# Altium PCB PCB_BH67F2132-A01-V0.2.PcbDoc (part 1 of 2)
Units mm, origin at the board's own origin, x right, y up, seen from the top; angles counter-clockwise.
Board outline 91.52 x 58.18 mm, 2 copper layers (Top Layer, Bottom Layer); 21 components, 47 nets, 172 pads, 84 vias.
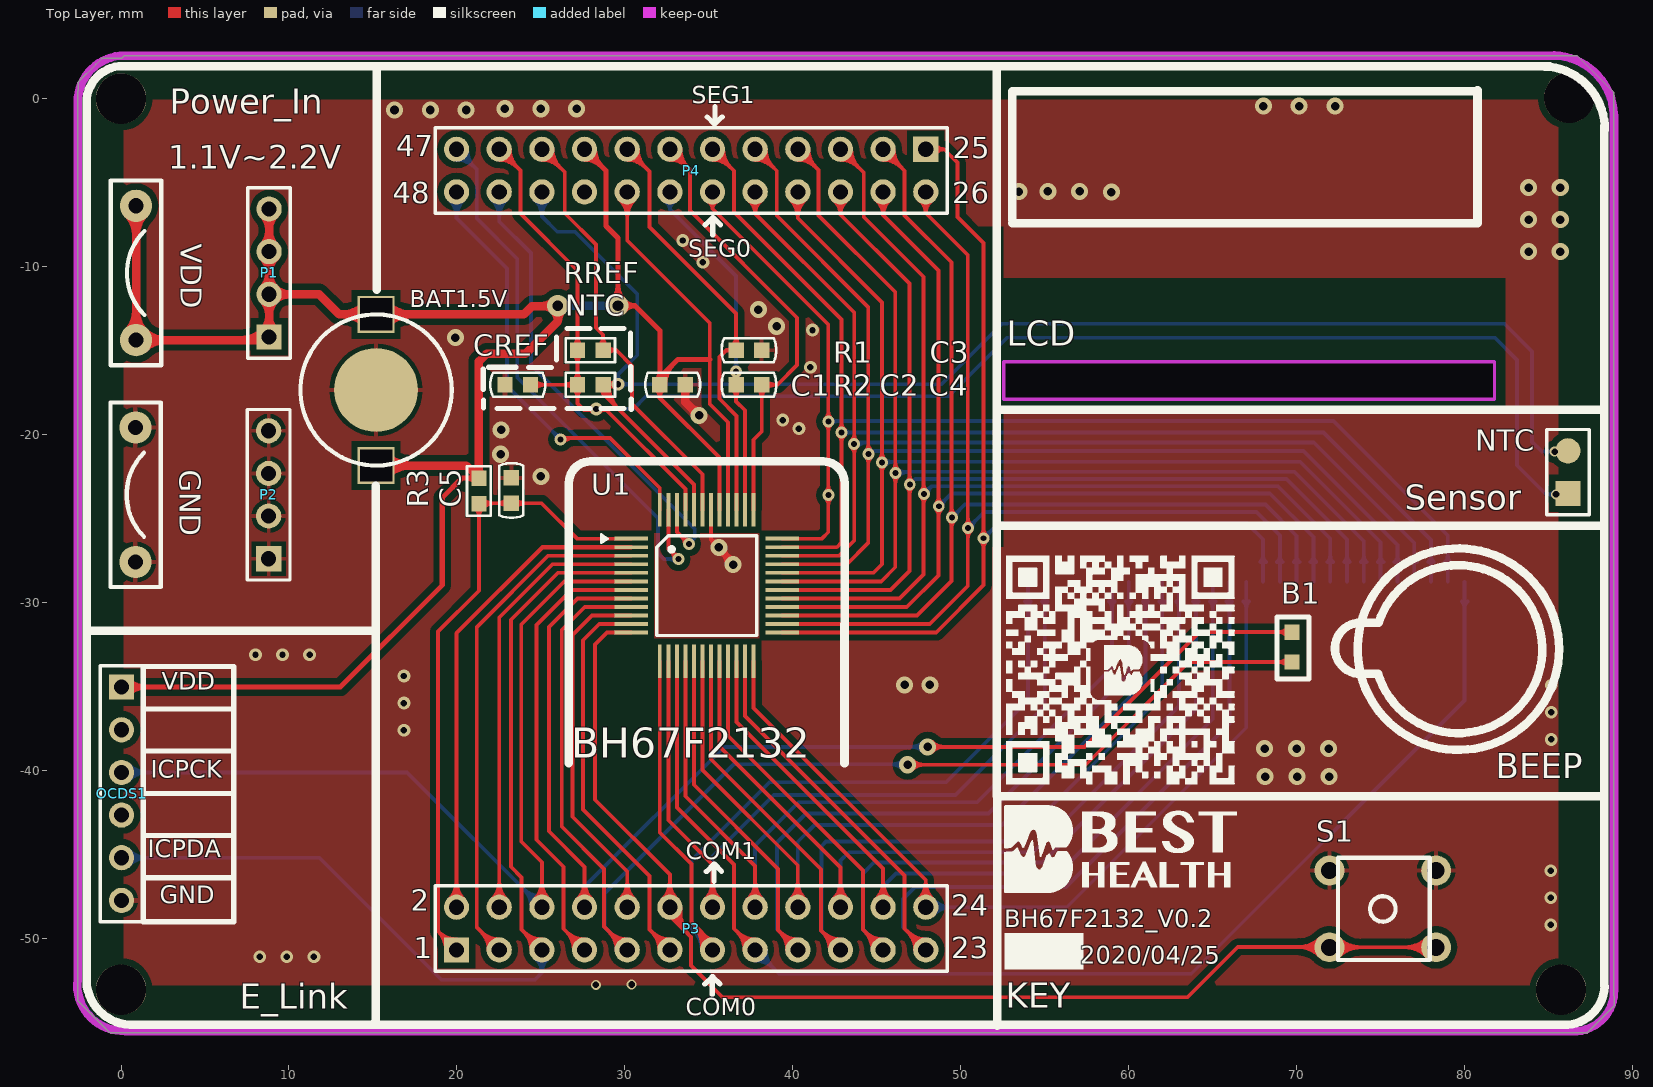
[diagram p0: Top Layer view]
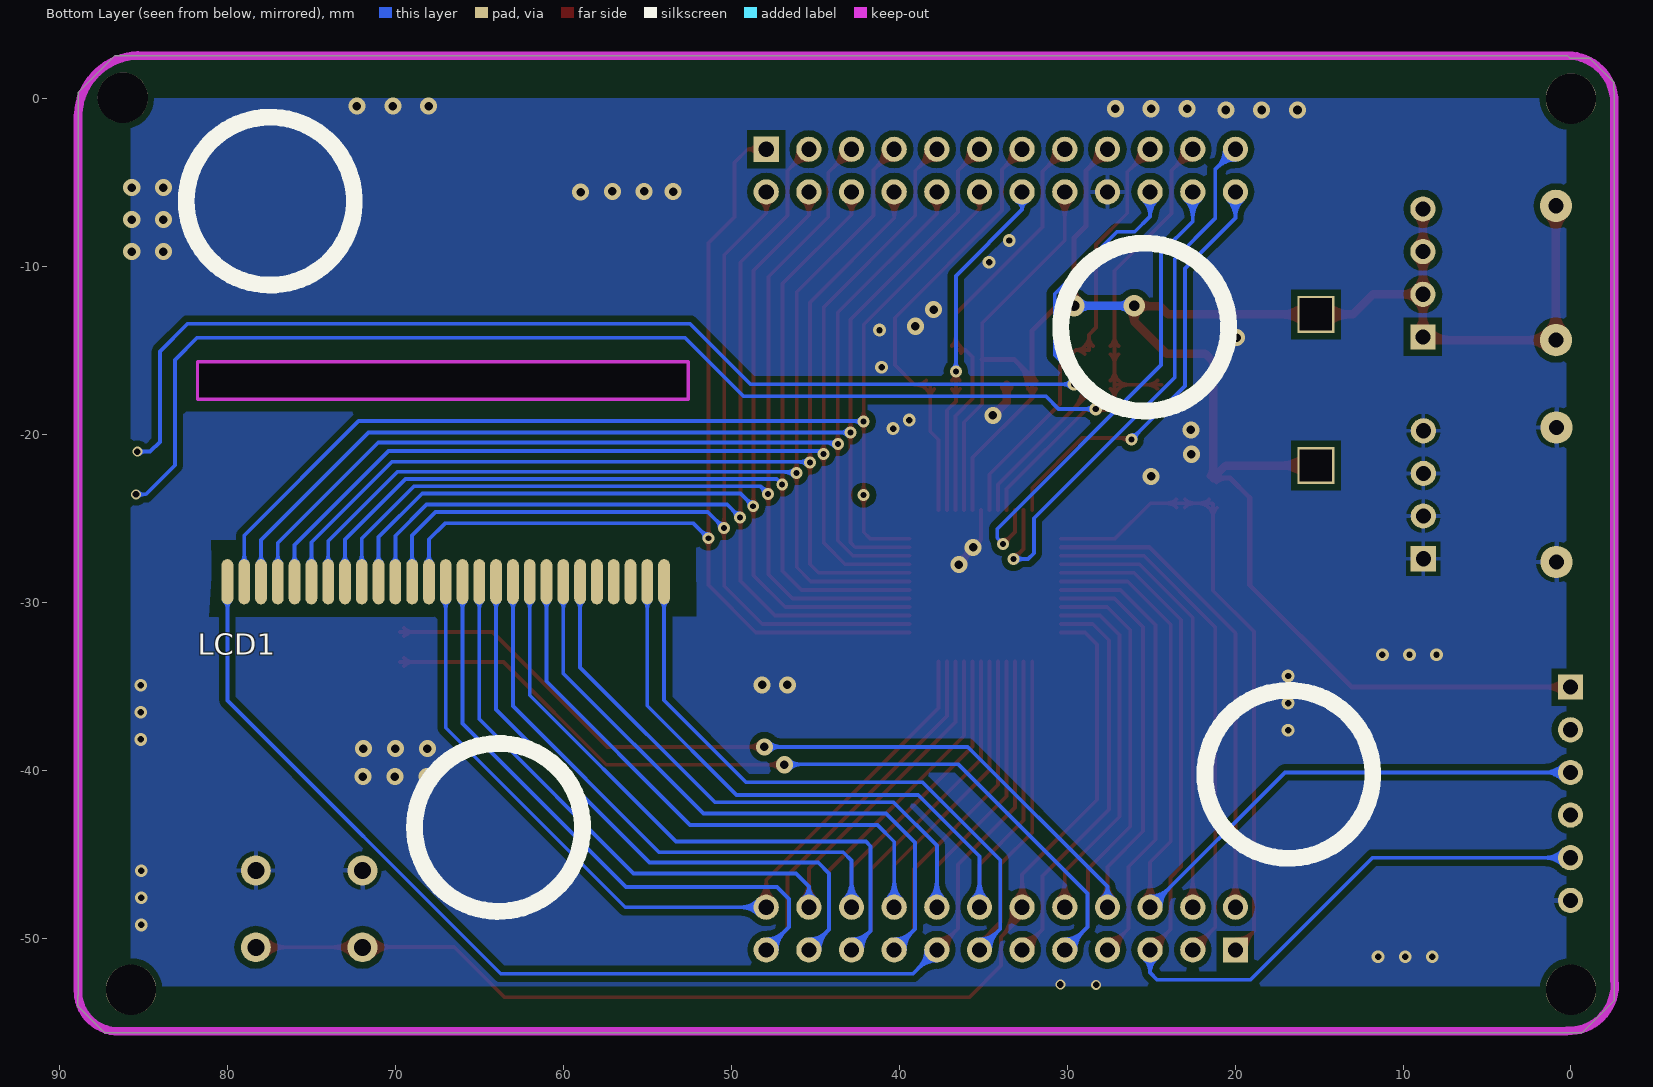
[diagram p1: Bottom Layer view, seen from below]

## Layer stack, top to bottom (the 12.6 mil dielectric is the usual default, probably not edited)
Top Layer: signal copper 0.0356
Dielectric: dielectric 0.32, FR-4, Dk 4.8
Bottom Layer: signal copper 0.0356

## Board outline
0.209,2.568 85.603,2.568 86.706,2.568 88.55,0.724 88.905,0.368 88.905,-0.978 88.905,-53.403 88.931,-53.429 88.931,-54.013 87.534,-55.41 87.33,-55.613 86.772,-55.613 -0.681,-55.613 -1.366,-54.927 -2.586,-53.708 -2.586,-52.794 -2.586,0.419 -2.535,0.47 -2.535,1.003 -1.493,2.045 -1.138,2.4 -0.706,2.4 0.042,2.4 0.209,2.568
cut-out: 52.583,-15.659 81.793,-15.659 81.793,-17.92 52.583,-17.92

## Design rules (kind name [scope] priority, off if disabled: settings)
Clearance Clearance_2 [InPolygon] p1: gap=0.381
Clearance [All] p2: gap=0.203
ComponentClearance [All] p1: gap=-1 collisioncheckmode=3 verticalgap=-1 showdistances=FALSE
HoleSize [All] p1: absolutevalues=TRUE maxlimit=25.4 minlimit=0.025 maxpercent=80.000 minpercent=20.000
HoleToHoleClearance [All] p1: gap=0 allowstackedmicrovias=TRUE
MinimumSolderMaskSliver [All] p1: minsoldermaskwidth=0
PolygonConnect PolygonConnect_1 [IsVIA and InNET('VSS')] p1: connectstyle=Direct reliefconductorwidth=0.254 reliefentries=4 polygonreliefangle="90 Angle"
PolygonConnect [All] p2: connectstyle=Relief reliefconductorwidth=0.254 reliefentries=4 polygonreliefangle="90 Angle"
RoutingVias [All] p1: holewidth=0.711 width=0.635 viastyle="Through Hole" minholewidth=0.025 minwidth=0.025 maxholewidth=2.54 maxwidth=2.54
SilkToSilkClearance [All] p1 off: silktosilkclearance=0
SilkscreenOverComponentPads [IsPad] p1: minsilkscreentomaskgap=-1
SolderMaskExpansion [All] p1: expansion=0.102
Width [All] p1: maxlimit=2.54 minlimit=0.025 preferedwidth=0.229
22 further rules are at their usual default settings.

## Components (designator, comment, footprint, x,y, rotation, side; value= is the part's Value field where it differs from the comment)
B1 "Beep" BEEP 79.634,-32.779 r180 top
BAT1.5V "BATTERY(1)" LR41H 15.189,-21.844 r90 top
C1 "2200pf" C0603 23.627,-17.031 r0 top
C2 "104" C0603 32.847,-17.031 r0 top
C3 "104" C0603 37.394,-14.973 r180 top
C4 "104" C0603 37.394,-17.031 r180 top
C5 "104" C0603 23.246,-23.33 r90 top
GND "CONNET*2" "CLIP POWER PIN - DUPLICATE" 0.869,-23.584 r90 top (schematic designator GND1)
LCD1 "LCD 27 Pin" "LCD 27 Pin" 67.007,-28.765 r180 bottom
NTC "NTC-Header" NTC 86.162,-23.508 r90 top (schematic designator NTC2)
OCDS1 "Header 4" HDR1X6 0.031,-35.039 r270 top
P1 "Header 4" HDR1X4 8.819,-14.186 r90 top
P2 "Header 4" HDR1X4 8.794,-27.394 r90 top
P3 "Header 12X2" HDR2X12 19.983,-50.686 r0 top locked
P4 "Header 12X2" HDR2X12 47.923,-3.01 r180 top locked
R1 "30k" R0603 27.945,-14.973 r180 top
R2 "MEB12-503F3950" R0603 27.945,-17.031 r180 top
R3 "100K" R0603 21.316,-23.355 r270 top
S1 "Switch" AN66 75.138,-48.247 r90 top
U1 "BH67F2132_48LQFP" LQFP_48 34.879,-28.994 r0 top
VDD "CONNET*2" "CLIP POWER PIN - DUPLICATE" 0.894,-10.376 r90 top (schematic designator VDD1)

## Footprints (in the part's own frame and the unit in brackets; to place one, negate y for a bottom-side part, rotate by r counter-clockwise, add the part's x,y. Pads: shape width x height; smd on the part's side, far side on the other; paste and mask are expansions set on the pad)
AN66 [mil] "DIP PUSH BOTTON (6MM*6MM)"
  round 70 hole 40: 1(-90,125) 1(-90,-125) 2(90,125) 2(90,-125)
  silkscreen extent -120,-110 120,105
BEEP [mil]
  rect 35.98x35.98 smd: 1(390,-40) 2(390,30)
  silkscreen extent -236,-236 425,236
C0603 [mil] "0603 CAPACITOR"
  rect 36x36 smd: 1(-30,0) 2(30,0)
  Top Layer pour cut-out: 10,15 10,-15 -10,-15 -10,15
  silkscreen extent -64,-28 64,28, body extent -51,-18 52,21, height 35
"CLIP POWER PIN - DUPLICATE" [mm] "USE PAPER CLIP AS POWER PIN(PITCH=8MM)"
  round 1.924 hole 0.9: 1(-4,0) 2(4,0)
  silkscreen extent -5.5,-1.5 5.5,1.5
HDR1X4 [mm] "Connector; Header; 4 Position"
  rect 1.5x1.5 hole 0.9: 1(0,0)
  round 1.5 hole 0.9: 2(2.54,0) 3(5.08,0) 4(7.62,0)
  silkscreen extent -1.27,-1.27 8.89,1.27
HDR1X6 [mm] "Connector; Header; 6 Position"
  rect 1.5x1.5 hole 0.9: 1(0,0)
  round 1.5 hole 0.9: 2(2.54,0) 3(5.08,0) 4(7.62,0) 5(10.16,0) 6(12.7,0)
  silkscreen extent -1.27,-1.27 13.97,1.27
HDR2X12 [mm] "Connector; Header; 12x2 Position"
  rect 1.5x1.5 hole 0.9: 1(0,0)
  round 1.5 hole 0.9: 2(0,2.54) 3(2.54,0) 4(2.54,2.54) 5(5.08,0) 6(5.08,2.54) 7(7.62,0) 8(7.62,2.54) 9(10.16,0) 10(10.16,2.54) 11(12.7,0) 12(12.7,2.54) 13(15.24,0) 14(15.24,2.54) 15(17.78,0) 16(17.78,2.54) 17(20.32,0) 18(20.32,2.54) 19(22.86,0) 20(22.86,2.54) 21(25.4,0) 22(25.4,2.54) 23(27.94,0) 24(27.94,2.54)
  silkscreen extent -1.27,-1.27 29.21,3.81
"LCD 27 Pin" [mm]
  oval 0.7x2.7 smd: 1(-13,0) 2(-12,0) 3(-11,0) 4(-10,0) 5(-9,0) 6(-8,0) 7(-7,0) 8(-6,0) 9(-5,0) 10(-4,0) 11(-3,0) 12(-2,0) 13(-1,0) 14(0,0) 15(1,0) 16(2,0) 17(3,0) 18(4,0) 19(5,0) 20(6,0) 21(7,0) 22(8,0) 23(9,0) 24(10,0) 25(11,0) 26(12,0) 27(13,0)
LQFP_48 [mm]
  rect 2x0.23 smd: 1(-4.505,2.794) 2(-4.505,2.286) 3(-4.505,1.778) 4(-4.505,1.27) 5(-4.505,0.762) 6(-4.505,0.254) 7(-4.505,-0.254) 8(-4.505,-0.762) 9(-4.505,-1.27) 10(-4.505,-1.778) 11(-4.505,-2.286) 12(-4.505,-2.794) 25(4.505,-2.794) 26(4.505,-2.286) 27(4.505,-1.778) 28(4.505,-1.27) 29(4.505,-0.762) 30(4.505,-0.254) 31(4.505,0.254) 32(4.505,0.762) 33(4.505,1.27) 34(4.505,1.778) 35(4.505,2.286) 36(4.505,2.794)
  rect 0.23x2 smd: 13(-2.794,-4.505) 14(-2.286,-4.505) 15(-1.778,-4.505) 16(-1.27,-4.505) 17(-0.762,-4.505) 18(-0.254,-4.505) 19(0.254,-4.505) 20(0.762,-4.505) 21(1.27,-4.505) 22(1.778,-4.505) 23(2.286,-4.505) 24(2.794,-4.505) 37(2.794,4.505) 38(2.286,4.505) 39(1.778,4.505) 40(1.27,4.505) 41(0.762,4.505) 42(0.254,4.505) 43(-0.254,4.505) 44(-0.762,4.505) 45(-1.27,4.505) 46(-1.778,4.505) 47(-2.286,4.505) 48(-2.794,4.505)
  silkscreen extent -6.28,-2.97 2.97,3.05
LR41H [mm]
  rect 2.2x2.2 hole 1.9 square: 1(0,0) 1(9,0)
  round 5 smd: 2(4.5,0)
  silkscreen extent 0,-4.5 9,4.5
NTC [mm] "Connector; Header; 2 Position"
  rect 1.5x1.5 smd: 1(0,0)
  round 1.5 smd: 2(2.54,0)
  silkscreen extent -1.27,-1.27 3.81,1.27
R0603 [mil] "0603 RESISTOR"
  rect 36x36 smd: 1(-30,0) 2(30,0)
  Top Layer pour cut-out: 10,15 10,-15 -10,-15 -10,15
  silkscreen extent -58,-28 58,28, body extent -31,-16 32,16, height 18

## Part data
BAT1.5V: "Singlecell Battery"
C1 C2 C3 C4 C5: library part CAP(1)
GND VDD: "2CONNET*2.54"
NTC: library part "Header 2", "Header, 2-Pin"
OCDS1: library part "Header 6", "Header, 6-Pin"
P1 P2: "Header, 4-Pin"
P3 P4: "Header, 12-Pin, Dual row"
R1 R3: library part RES(1)
R2: library part RES(1), "LINGEE NTC"
S1: library part Switch_4P

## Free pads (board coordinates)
  round 3 hole 3: 1(0,-53.061) 1(0,0) 1(85.75,-53.061) 1(86.238,0.064)

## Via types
v1: diameter 1.016, hole 0.508, Top Layer to Bottom Layer, tented both sides, 38 vias
v2: diameter 0.762, hole 0.381, Top Layer to Bottom Layer, tented both sides, 23 vias
v3: diameter 0.711, hole 0.356, Top Layer to Bottom Layer, tented both sides, 17 vias
v4: diameter 0.6, hole 0.4, Top Layer to Bottom Layer, tented both sides, 4 vias
v5: diameter 1.27, hole 0.635, Top Layer to Bottom Layer, tented both sides, 2 vias

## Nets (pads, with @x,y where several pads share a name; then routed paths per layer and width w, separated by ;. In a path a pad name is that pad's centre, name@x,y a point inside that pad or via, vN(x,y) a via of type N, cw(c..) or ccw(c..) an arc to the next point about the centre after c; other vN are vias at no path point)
C1: C4.2 P4.14 U1.38 | length 27.1
  Top Layer w0.229: C4.2@36.39,-17.273 cw(c35.804,-17.858) 36.632,-17.858 cw(c37.46,-17.858) C4.2@36.874,-17.273 ; C4.2@36.398,-16.78 ccw(c35.899,-16.243) v3(36.632,-16.243) ; v3@36.461,-16.414 cw(c36.049,-16.826) 36.632,-16.826 cw(c37.215,-16.826) v3@36.803,-16.414 ; v3@36.477,-16.428 cw(c36.363,-16.564) 36.534,-16.609 cw(c36.705,-16.655) v3@36.674,-16.481 ; v3@36.59,-16.481 cw(c36.559,-16.655) 36.73,-16.609 cw(c36.901,-16.564) v3@36.787,-16.428 ; C4.2@36.866,-16.78 cw(c37.365,-16.243) v3(36.632,-16.243) ; U1.38@37.165,-24.489 37.165,-18.555 36.632,-18.021 C4.2@36.632,-17.031 v3(36.632,-16.243)
  Bottom Layer w0.229: P4.14@32.386,-6.112 cw(c32.126,-6.605) 32.683,-6.605 ; P4.14@32.683,-5.55 32.683,-6.605 ; P4.14@32.98,-6.112 ccw(c33.24,-6.605) 32.683,-6.605 ; v3@36.461,-16.073 ccw(c36.049,-15.661) 36.632,-15.661 ccw(c37.215,-15.661) v3@36.803,-16.073 ; v3(36.632,-16.243) 36.632,-10.554 32.683,-6.605
C2: C4.1 P4.13 U1.37 | length 32.8
  Top Layer w0.229: P4.13@32.683,-3.645 cw(c32.683,-5.18) 33.768,-4.095 cw(c34.853,-3.01) P4.13@33.319,-3.01 ; P4.13@32.683,-3.417 cw(c32.683,-4.4) 33.378,-3.705 cw(c34.073,-3.01) P4.13@33.09,-3.01 ; P4.13@32.683,-3.01 33.889,-4.216 33.889,-6.667 40.265,-13.043 40.265,-15.862 39.096,-17.031 C4.1@38.156,-17.031 38.156,-19.825 37.673,-20.307 U1.37@37.673,-24.489 ; C4.1@37.914,-17.273 cw(c37.328,-17.858) 38.156,-17.858 cw(c38.984,-17.858) 38.398,-17.273 cw(c38.984,-17.858) 38.984,-17.031 cw(c38.984,-16.203) C4.1@38.398,-16.788
COM0: LCD1.27 P3.13 U1.13 | length 64.9
  Top Layer w0.229: U1.13@32.085,-33.499 32.085,-43.701 33.965,-45.58 33.965,-49.035 ; 34.329,-49.399 cw(c33.147,-50.581) P3.13@34.817,-50.665 ; P3.13@34.588,-50.654 ccw(c32.454,-50.546) 33.965,-49.035 ; 34.693,-49.763 cw(c33.84,-50.616) P3.13@35.045,-50.677 ; 34.809,-49.878 ccw(c35.223,-49.464) P3.13@35.223,-50.05 ; P3.13@35.223,-50.686 35.223,-50.293 33.965,-49.035
  Bottom Layer w0.229: P3.13@34.587,-50.686 ccw(c33.053,-50.686) 34.138,-49.6 ccw(c35.223,-48.515) P3.13@35.223,-50.05 ; P3.13@34.816,-50.686 ccw(c33.833,-50.686) 34.528,-49.991 ccw(c35.223,-49.296) P3.13@35.223,-50.279 ; P3.13@35.223,-50.686 33.99,-49.453 33.99,-45.326 38.613,-40.703 49.129,-40.703 54.007,-35.825 LCD1.27@54.007,-28.765 ; LCD1.27@53.841,-29.932 cw(c53.438,-30.334) 54.007,-30.334 cw(c54.576,-30.334) LCD1.27@54.174,-29.932
COM1: LCD1.26 P3.14 U1.14 | length 58.5
  Top Layer w0.229: U1.14@32.593,-33.499 32.593,-42.964 35.223,-45.594 P3.14@35.223,-48.146 ; P3.14@34.774,-47.696 ccw(c33.688,-46.611) 35.223,-46.611 ccw(c36.758,-46.611) P3.14@35.673,-47.696 ; P3.14@34.935,-47.858 ccw(c34.24,-47.163) 35.223,-47.163 ccw(c36.206,-47.163) P3.14@35.511,-47.858
  Bottom Layer w0.229: P3.14@34.774,-47.696 ccw(c33.688,-46.611) 35.223,-46.611 ccw(c36.758,-46.611) P3.14@35.673,-47.696 ; P3.14@34.935,-47.858 ccw(c34.24,-47.163) 35.223,-47.163 ccw(c36.206,-47.163) P3.14@35.511,-47.858 ; P3.14@35.223,-48.146 35.223,-45.109 38.867,-41.465 49.688,-41.465 55.007,-36.146 LCD1.26@55.007,-28.765 ; LCD1.26@54.841,-29.932 cw(c54.438,-30.334) 55.007,-30.334 cw(c55.576,-30.334) LCD1.26@55.174,-29.932
COM2: LCD1.1 P3.15 U1.15 | length 84.6
  Top Layer w0.229: U1.15@33.101,-33.499 33.101,-42.202 36.505,-45.606 36.505,-49.427 P3.15@37.763,-50.686 ; P3.15@37.127,-50.686 ccw(c35.593,-50.686) 36.678,-49.6 ccw(c37.763,-48.515) P3.15@37.763,-50.05 ; P3.15@37.356,-50.686 ccw(c36.373,-50.686) 37.068,-49.991 ccw(c37.763,-49.296) P3.15@37.763,-50.279
  Bottom Layer w0.229: P3.15@37.763,-51.321 cw(c37.763,-52.856) 38.848,-51.771 cw(c39.934,-50.686) P3.15@38.399,-50.686 ; P3.15@37.763,-51.093 cw(c37.763,-52.076) 38.458,-51.381 cw(c39.153,-50.686) P3.15@38.17,-50.686 ; P3.15@37.763,-50.686 39.186,-52.108 63.734,-52.108 80.007,-35.834 LCD1.1@80.007,-28.765 ; LCD1.1@79.841,-29.932 cw(c79.438,-30.334) 80.007,-30.334 cw(c80.576,-30.334) LCD1.1@80.174,-29.932
ICPCK: OCDS1.3 P3.6 U1.6 | length 65.2
  Top Layer w0.229: P3.6@24.614,-47.696 ccw(c23.528,-46.611) 25.063,-46.611 ccw(c26.598,-46.611) P3.6@25.513,-47.696 ; P3.6@24.775,-47.858 ccw(c24.08,-47.163) 25.063,-47.163 ccw(c26.046,-47.163) P3.6@25.351,-47.858 ; P3.6@25.063,-48.146 25.063,-45.467 23.83,-44.234 23.83,-31.305 26.396,-28.74 U1.6@30.374,-28.74
  Bottom Layer w0.229: OCDS1.3@0.031,-40.119 17.037,-40.119 P3.6@25.063,-48.146 ; OCDS1.3@0.318,-40.407 cw(c1.013,-41.102) 1.013,-40.119 cw(c1.013,-39.136) OCDS1.3@0.318,-39.831 ; OCDS1.3@0.48,-40.569 cw(c1.565,-41.654) 1.565,-40.119 cw(c1.565,-38.584) OCDS1.3@0.48,-39.67 ; P3.6@24.427,-48.146 ccw(c22.893,-48.146) 23.978,-47.06 ccw(c25.063,-45.975) P3.6@25.063,-47.51 ; P3.6@24.656,-48.146 ccw(c23.673,-48.146) 24.368,-47.451 ccw(c25.063,-46.756) P3.6@25.063,-47.739
ICPDA: OCDS1.5 P3.5 U1.5 | length 69.5
  Top Layer w0.229: P3.5@24.427,-50.686 ccw(c22.893,-50.686) 23.978,-49.6 ccw(c25.063,-48.515) P3.5@25.063,-50.05 ; P3.5@24.656,-50.686 ccw(c23.673,-50.686) 24.368,-49.991 ccw(c25.063,-49.296) P3.5@25.063,-50.279 ; P3.5@25.063,-50.686 23.856,-49.478 23.856,-46.368 23.221,-45.733 23.221,-31.026 26.015,-28.232 U1.5@30.374,-28.232
  Bottom Layer w0.229: OCDS1.5@0.031,-45.199 11.816,-45.199 19.081,-52.464 24.643,-52.464 25.063,-52.044 ; OCDS1.5@0.318,-45.487 cw(c1.013,-46.182) 1.013,-45.199 cw(c1.013,-44.216) OCDS1.5@0.318,-44.911 ; OCDS1.5@0.48,-45.649 cw(c1.565,-46.734) 1.565,-45.199 cw(c1.565,-43.664) OCDS1.5@0.48,-44.75 ; P3.5@24.656,-51.174 cw(c23.93,-52.044) 25.063,-52.044 ; P3.5@24.802,-50.998 cw(c24.338,-51.555) 25.063,-51.555 cw(c25.788,-51.555) P3.5@25.324,-50.998 ; P3.5@25.063,-50.686 25.063,-52.044 ; P3.5@25.47,-51.174 ccw(c26.196,-52.044) 25.063,-52.044
PA1: P3.7 U1.7 | length 31
  Top Layer w0.229: P3.7@26.967,-50.686 ccw(c25.433,-50.686) 26.518,-49.6 ccw(c27.603,-48.515) P3.7@27.603,-50.05 ; P3.7@27.196,-50.686 ccw(c26.213,-50.686) 26.908,-49.991 ccw(c27.603,-49.296) P3.7@27.603,-50.279 ; P3.7@27.603,-50.686 26.345,-49.427 26.345,-45.733 24.745,-44.132 24.745,-31.331 26.828,-29.248 U1.7@30.374,-29.248
PA3: B1.1 P3.8 U1.8 | length 83.8
  Top Layer w0.229: P3.8@27.154,-47.696 ccw(c26.068,-46.611) 27.603,-46.611 ccw(c29.138,-46.611) P3.8@28.053,-47.696 ; P3.8@27.315,-47.858 ccw(c26.62,-47.163) 27.603,-47.163 ccw(c28.586,-47.163) P3.8@27.891,-47.858 ; P3.8@27.603,-48.146 27.603,-45.746 25.481,-43.624 25.481,-31.458 27.183,-29.756 U1.8@30.374,-29.756 ; v1(48.037,-38.595) 57.384,-38.595 64.216,-31.763 B1.1@69.728,-31.763 ; v1@48.315,-38.874 cw(c48.987,-39.546) 48.987,-38.595 cw(c48.987,-37.645) v1@48.315,-38.317 ; B1.1@69.486,-32.005 ccw(c68.901,-32.59) 68.901,-31.763 ccw(c68.901,-30.935) B1.1@69.486,-31.52
  Bottom Layer w0.229: P3.8@27.235,-47.628 ccw(c26.726,-46.913) 27.603,-46.913 ; P3.8@27.367,-47.814 ccw(c27.041,-47.356) 27.603,-47.356 ccw(c28.165,-47.356) P3.8@27.839,-47.814 ; P3.8@27.603,-48.146 27.603,-46.913 ; P3.8@27.972,-47.628 cw(c28.48,-46.913) 27.603,-46.913 ; v1@47.758,-38.874 ccw(c47.086,-39.546) 47.086,-38.595 ccw(c47.086,-37.645) v1@47.758,-38.317 ; v1(48.037,-38.595) 35.921,-38.595 27.603,-46.913
PA4: B1.2 P3.9 U1.9 | length 88.1
  Top Layer w0.229: P3.9@29.507,-50.686 ccw(c27.973,-50.686) 29.058,-49.6 ccw(c30.143,-48.515) P3.9@30.143,-50.05 ; P3.9@29.736,-50.686 ccw(c28.753,-50.686) 29.448,-49.991 ccw(c30.143,-49.296) P3.9@30.143,-50.279 ; P3.9@30.143,-50.686 28.758,-49.3 28.758,-45.86 26.243,-43.345 26.243,-31.636 27.615,-30.264 U1.9@30.374,-30.264 ; v1(46.843,-39.662) 57.446,-39.662 63.567,-33.541 B1.2@69.728,-33.541 ; v1@47.121,-39.94 cw(c47.793,-40.612) 47.793,-39.662 cw(c47.793,-38.712) v1@47.121,-39.384 ; B1.2@69.486,-33.783 ccw(c68.901,-34.368) 68.901,-33.541 ccw(c68.901,-32.713) B1.2@69.486,-33.298
  Bottom Layer w0.229: P3.9@29.507,-50.686 ccw(c27.973,-50.686) 29.058,-49.6 ccw(c30.143,-48.515) P3.9@30.143,-50.05 ; P3.9@29.736,-50.686 ccw(c28.753,-50.686) 29.448,-49.991 ccw(c30.143,-49.296) P3.9@30.143,-50.279 ; P3.9@30.143,-50.686 28.783,-49.326 28.783,-47.333 36.48,-39.637 v1@46.843,-39.637 ; 45.831,-39.637 cw(c45.831,-40.674) v1@46.564,-39.94 ; 45.954,-39.637 ccw(c45.954,-38.773) v1@46.564,-39.384
PA5: P3.10 U1.10 | length 25.5
  Top Layer w0.229: P3.10@29.694,-47.696 ccw(c28.608,-46.611) 30.143,-46.611 ccw(c31.678,-46.611) P3.10@30.593,-47.696 ; P3.10@29.855,-47.858 ccw(c29.16,-47.163) 30.143,-47.163 ccw(c31.126,-47.163) P3.10@30.431,-47.858 ; P3.10@30.143,-48.146 30.143,-46.026 26.878,-42.761 26.878,-31.94 28.047,-30.772 U1.10@30.374,-30.772
PA6: P3.11 U1.11 | length 27.8
  Top Layer w0.229: U1.11@30.374,-31.28 28.479,-31.28 27.513,-32.245 27.513,-42.329 31.476,-46.291 31.476,-49.478 P3.11@32.683,-50.686 ; P3.11@32.047,-50.686 ccw(c30.513,-50.686) 31.598,-49.6 ccw(c32.683,-48.515) P3.11@32.683,-50.05 ; P3.11@32.276,-50.686 ccw(c31.293,-50.686) 31.988,-49.991 ccw(c32.683,-49.296) P3.11@32.683,-50.279
PA7: P3.12 S1.1 U1.12 | length 94.7
  Top Layer w0.229: U1.12@30.374,-31.788 28.936,-31.788 28.225,-32.499 28.225,-41.745 32.683,-46.203 P3.12@32.683,-48.146 32.683,-48.667 33.94,-49.924 ; P3.12@32.234,-47.696 ccw(c31.148,-46.611) 32.683,-46.611 ccw(c34.218,-46.611) P3.12@33.133,-47.696 ; P3.12@32.395,-47.858 ccw(c31.7,-47.163) 32.683,-47.163 ccw(c33.666,-47.163) P3.12@32.971,-47.858 ; P3.12@32.633,-48.141 ccw(c33.566,-48.226) 32.904,-48.888 ; P3.12@32.861,-48.162 ccw(c34.199,-48.283) 33.249,-49.233 ; P3.12@33.089,-48.182 ccw(c34.832,-48.34) 33.594,-49.578 ; P3.12@33.316,-48.203 ccw(c35.466,-48.398) 33.94,-49.924 ; 70.032,-50.508 cw(c70.032,-52.465) S1.1@71.416,-51.081 ; 70.154,-50.508 ccw(c70.154,-48.724) S1.1@71.416,-49.985 ; 70.584,-50.508 cw(c70.584,-51.913) S1.1@71.577,-50.919 ; 70.706,-50.508 ccw(c70.706,-49.276) S1.1@71.577,-50.147 ; S1.1@72.35,-50.919 cw(c73.282,-51.852) 73.282,-50.533 cw(c73.282,-49.215) S1.1@72.35,-50.147 ; S1.1@72.511,-51.081 cw(c73.834,-52.403) 73.834,-50.533 cw(c73.834,-48.663) S1.1@72.511,-49.985 ; S1.1@77.766,-51.081 ccw(c76.443,-52.403) 76.443,-50.533 ccw(c76.443,-48.663) S1.1@77.766,-49.985 ; S1.1@77.927,-50.919 ccw(c76.995,-51.852) 76.995,-50.533 ccw(c76.995,-49.215) S1.1@77.927,-50.147 ; S1.1@78.313,-50.533 S1.1@71.963,-50.533 71.938,-50.508 66.502,-50.508 63.505,-53.505 35.819,-53.505 33.94,-51.625 33.94,-49.924
PB0: C5.1 P3.1 R3.2 U1.1 | length 47.1
  Top Layer w0.229: P3.1@19.347,-50.686 ccw(c17.813,-50.686) 18.898,-49.6 ccw(c19.983,-48.515) P3.1@19.983,-50.05 ; P3.1@19.576,-50.686 ccw(c18.593,-50.686) 19.288,-49.991 ccw(c19.983,-49.296) P3.1@19.983,-50.279 ; P3.1@19.983,-50.686 18.877,-49.58 18.877,-31.737 21.316,-29.299 R3.2@21.316,-24.117 21.341,-24.092 C5.1@23.246,-24.092 25.05,-24.092 27.158,-26.2 U1.1@30.374,-26.2 ; R3.2@21.073,-24.36 cw(c20.488,-24.945) 21.316,-24.945 cw(c22.144,-24.945) 21.558,-24.36 cw(c22.205,-25.006) 22.205,-24.092 ; R3.2@21.558,-23.875 ccw(c22.082,-23.351) 22.082,-24.092 ; C5.1@23.004,-24.334 ccw(c22.418,-24.92) 22.418,-24.092 ccw(c22.418,-23.264) C5.1@23.004,-23.849 ; C5.1@23.489,-24.334 cw(c24.074,-24.92) 24.074,-24.092 cw(c24.074,-23.264) C5.1@23.489,-23.849
PB1: P3.2 U1.2 | length 32.6
  Top Layer w0.254: P3.2@19.543,-47.705 ccw(c18.479,-46.642) 19.983,-46.642 ccw(c21.487,-46.642) P3.2@20.424,-47.705 ; P3.2@19.722,-47.885 ccw(c19.092,-47.255) 19.983,-47.255 ccw(c20.874,-47.255) P3.2@20.244,-47.885 ; P3.2@19.983,-48.146 19.983,-31.825 25.1,-26.708 U1.2@30.374,-26.708
PB2: P3.3 U1.3 | length 34.7
  Top Layer w0.229: P3.3@21.887,-50.686 ccw(c20.353,-50.686) 21.438,-49.6 ccw(c22.523,-48.515) P3.3@22.523,-50.05 ; P3.3@22.116,-50.686 ccw(c21.133,-50.686) 21.828,-49.991 ccw(c22.523,-49.296) P3.3@22.523,-50.279 ; P3.3@22.523,-50.686 21.189,-49.351 21.189,-31.458 25.431,-27.216 U1.3@30.374,-27.216
PB3: P3.4 U1.4 | length 30.4
  Top Layer w0.229: P3.4@22.074,-47.696 ccw(c20.988,-46.611) 22.523,-46.611 ccw(c24.058,-46.611) P3.4@22.973,-47.696 ; P3.4@22.235,-47.858 ccw(c21.54,-47.163) 22.523,-47.163 ccw(c23.506,-47.163) P3.4@22.811,-47.858 ; P3.4@22.523,-48.146 22.523,-30.885 25.685,-27.724 U1.4@30.374,-27.724
PLCD: C3.2 P4.15 U1.39 | length 31.3
  Top Layer w0.229: P4.15@30.143,-3.645 cw(c30.143,-5.18) 31.228,-4.095 cw(c32.313,-3.01) P4.15@30.779,-3.01 ; P4.15@30.143,-3.417 cw(c30.143,-4.4) 30.838,-3.705 cw(c31.533,-3.01) P4.15@30.55,-3.01 ; P4.15@30.143,-3.01 31.476,-4.343 31.476,-7.633 36.632,-12.789 C3.2@36.632,-14.973 36.048,-14.973 ; C3.2@36.333,-15.14 ccw(c36.048,-15.299) 36.048,-14.973 ; C3.2@36.333,-14.806 cw(c36.048,-14.647) 36.048,-14.973 ; C3.2@36.39,-14.731 ccw(c35.804,-14.145) 36.632,-14.145 ccw(c37.46,-14.145) C3.2@36.874,-14.731 ; U1.39@36.657,-24.489 36.657,-18.885 35.641,-17.869 35.641,-15.38 36.048,-14.973
RCIN: C1.2 NTC.1 P4.21 R1.2 R2.2 U1.45 | length 111.3
  Top Layer w0.229: P4.21@22.523,-3.645 cw(c22.523,-5.18) 23.608,-4.095 cw(c24.693,-3.01) P4.21@23.159,-3.01 ; P4.21@22.523,-3.417 cw(c22.523,-4.4) 23.218,-3.705 cw(c23.913,-3.01) P4.21@22.93,-3.01 ; P4.21@22.523,-3.01 23.78,-4.266 23.78,-6.845 27.183,-10.249 R1.2@27.183,-14.973 R2.2@27.183,-17.031 ; C1.2@24.389,-17.031 R2.2@27.183,-17.031 ; C1.2@24.632,-17.273 cw(c25.217,-17.858) 25.217,-17.031 cw(c25.217,-16.203) C1.2@24.632,-16.788 ; R1.2@26.941,-15.216 cw(c26.355,-15.801) 27.183,-15.801 cw(c28.011,-15.801) R1.2@27.426,-15.216 ; R1.2@26.941,-14.731 ccw(c26.355,-14.145) 27.183,-14.145 ccw(c28.011,-14.145) R1.2@27.426,-14.731 ; R2.2@27.426,-17.273 ccw(c28.011,-17.858) 27.183,-17.858 ccw(c26.355,-17.858) 26.941,-17.273 ccw(c26.355,-17.858) 26.355,-17.031 ccw(c26.355,-16.203) 26.941,-16.788 ccw(c26.355,-16.203) 27.183,-16.203 ccw(c28.011,-16.203) R2.2@27.426,-16.788 ; 27.78,-18.529 cw(c27.78,-19) v2@28.112,-18.667 ; v2@28.107,-18.295 cw(c27.564,-17.783) 27.564,-18.529 ; v2@28.489,-18.667 cw(c28.822,-19) 28.822,-18.529 ; v2@28.523,-18.331 ccw(c28.892,-18.087) 28.892,-18.529 ; U1.45@33.609,-24.489 33.609,-23.247 28.892,-18.529 ; R2.2@27.183,-17.031 27.183,-18.148 27.564,-18.529 ; 27.564,-18.529 28.892,-18.529
  Bottom Layer w0.229: v2(28.301,-18.478) 30.511,-18.478 31.273,-17.716 49.282,-17.716 52.762,-14.237 81.819,-14.237 83.139,-15.557 83.139,-21.831 84.867,-23.558 v4(85.451,-23.558) ; v2@28.489,-18.667 cw(c28.945,-19.122) 28.945,-18.478 cw(c28.945,-17.835) v2@28.489,-18.29 ; v4@85.319,-23.69 ccw(c85.002,-24.007) 85.002,-23.558 ccw(c85.002,-23.11) v4@85.319,-23.427
RCIN1: P4.22 U1.46 | length 33.1
  Top Layer w0.229: U1.46@33.101,-24.489 33.101,-25.794 v3(33.813,-26.505) ; v3@33.571,-26.505 ccw(c32.989,-26.505) 33.401,-26.093 ccw(c33.813,-25.681) v3@33.813,-26.264
  Bottom Layer w0.229: P4.22@22.073,-5.999 cw(c20.988,-7.085) 22.523,-7.085 cw(c24.058,-7.085) P4.22@22.973,-5.999 ; P4.22@22.235,-5.838 cw(c21.54,-6.533) 22.523,-6.533 cw(c23.506,-6.533) P4.22@22.811,-5.838 ; P4.22@22.523,-5.55 22.523,-7.308 24.409,-9.195 24.409,-15.857 34.168,-25.616 34.168,-26.149 v3(33.813,-26.505)
RREF: P4.19 R1.1 U1.43 | length 32.4
  Top Layer w0.229: P4.19@25.063,-3.645 cw(c25.063,-5.18) 26.148,-4.095 cw(c27.233,-3.01) P4.19@25.699,-3.01 ; P4.19@25.063,-3.417 cw(c25.063,-4.4) 25.758,-3.705 cw(c26.453,-3.01) P4.19@25.47,-3.01 ; P4.19@25.063,-3.01 26.421,-4.368 26.421,-6.82 28.275,-8.674 28.275,-13.627 28.707,-14.059 R1.1@28.707,-14.973 29.495,-14.973 ; R1.1@28.465,-14.731 ccw(c27.879,-14.145) 28.707,-14.145 ccw(c29.535,-14.145) R1.1@28.95,-14.731 ; R1.1@28.958,-15.207 cw(c29.495,-15.706) 29.495,-14.973 ; R1.1@28.958,-14.74 ccw(c29.495,-14.241) 29.495,-14.973 ; U1.43@34.625,-24.489 34.625,-22.365 30.434,-18.174 30.434,-15.913 29.495,-14.973
RREF1: P4.24 U1.48 | length 31.5
  Top Layer w0.229: v3@26.167,-20.206 29.114,-20.206 32.085,-23.177 U1.48@32.085,-24.489 ; v3@26.338,-20.452 cw(c26.934,-21.048) 26.934,-20.206 ; v3@26.338,-20.111 ccw(c26.566,-19.883) 26.566,-20.206
  Bottom Layer w0.229: P4.24@19.533,-5.999 cw(c18.448,-7.085) 19.983,-7.085 cw(c21.518,-7.085) P4.24@20.433,-5.999 ; P4.24@19.695,-5.838 cw(c19,-6.533) 19.983,-6.533 cw(c20.966,-6.533) P4.24@20.271,-5.838 ; P4.24@19.983,-5.55 19.983,-7.105 22.987,-10.109 22.987,-17.102 v3(26.167,-20.282) ; v3@25.926,-20.282 ccw(c25.343,-20.282) 25.755,-19.87 ccw(c26.167,-19.458) v3@26.167,-20.041
RSEN: NTC.2 P4.20 R2.1 U1.44 | length 103
  Top Layer w0.229: R2.1@28.565,-17.343 cw(c28.464,-17.564) 28.707,-17.564 ; R2.1@28.593,-17.031 ccw(c29.605,-17.031) 28.889,-17.746 ; R2.1@28.821,-17.031 ccw(c30.385,-17.031) 29.279,-18.136 ; R2.1@28.85,-17.343 ccw(c28.951,-17.564) 28.707,-17.564 ; R2.1@28.891,-17.031 ccw(c28.891,-16.3) v2@29.408,-16.817 ; R2.1@28.95,-17.273 cw(c29.535,-17.858) 29.535,-17.031 cw(c29.535,-16.203) R2.1@28.95,-16.788 ; R2.1@29.014,-17.031 cw(c29.014,-17.588) v2@29.408,-17.194 ; R2.1@29.05,-17.031 ccw(c31.166,-17.031) 29.67,-18.527 ; v2@29.342,-17.085 ccw(c29.132,-17.15) 29.189,-16.938 ccw(c29.231,-16.781) v2@29.369,-16.866 ; v2@29.343,-16.922 cw(c29.018,-16.815) 29.107,-17.145 cw(c29.201,-17.498) v2@29.429,-17.213 ; v2(29.596,-17.005) 29.571,-17.031 R2.1@28.707,-17.031 28.707,-17.564 ; U1.44@34.117,-24.489 34.117,-22.974 28.707,-17.564
  Bottom Layer w0.229: P4.20@24.63,-6.015 cw(c23.702,-7.011) 25.063,-7.011 cw(c26.424,-7.011) P4.20@25.496,-6.015 ; P4.20@24.785,-5.848 cw(c24.191,-6.486) 25.063,-6.486 cw(c25.935,-6.486) P4.20@25.341,-5.848 ; P4.20@25.063,-5.55 25.063,-7.011 25.977,-7.925 27.043,-7.925 30.739,-11.62 30.739,-15.278 29.596,-16.421 ; v2@29.422,-16.804 ccw(c29.09,-16.421) 29.596,-16.421 ; v2@29.771,-16.804 cw(c30.103,-16.421) 29.596,-16.421 ; v2@29.785,-17.194 cw(c30.24,-17.649) 30.24,-17.005 cw(c30.24,-16.361) v2@29.785,-16.817 ; v4@85.243,-21.15 ccw(c84.926,-21.467) 84.926,-21.018 ccw(c84.926,-20.57) v4@85.243,-20.887 ; v4(85.375,-21.018) 84.613,-21.018 84.028,-20.434 84.028,-15.049 82.377,-13.398 52.456,-13.398 48.849,-17.005 v2(29.596,-17.005) 29.596,-16.421
RSEN1: P4.23 U1.47 | length 39.3
  Top Layer w0.229: U1.47@32.593,-24.489 32.593,-26.81 v3(33.19,-27.407) ; v3@32.949,-27.407 ccw(c32.366,-27.407) 32.778,-26.995 ccw(c33.19,-26.583) v3@33.19,-27.165
  Bottom Layer w0.229: P4.23@19.983,-3.645 cw(c19.983,-5.18) 21.068,-4.095 cw(c22.153,-3.01) P4.23@20.619,-3.01 ; P4.23@19.983,-3.417 cw(c19.983,-4.4) 20.678,-3.705 cw(c21.373,-3.01) P4.23@20.39,-3.01 ; P4.23@19.983,-3.01 21.189,-4.216 21.189,-7.143 23.597,-9.55 23.597,-16.594 31.984,-24.981 31.984,-27.064 32.327,-27.407 v3(33.19,-27.407) ; v3@33.02,-27.577 ccw(c32.608,-27.989) 32.608,-27.407 ccw(c32.608,-26.824) v3@33.02,-27.236
SEG0: LCD1.2 P4.12 U1.36 | length 75
  Top Layer w0.229: P4.12@34.951,-6.124 cw(c34.748,-6.554) 35.223,-6.554 ; P4.12@35.223,-5.55 35.223,-6.554 ; P4.12@35.495,-6.124 ccw(c35.698,-6.554) 35.223,-6.554 ; U1.36@39.385,-26.2 41.737,-26.2 42.118,-25.819 v3(42.118,-23.609) v3(42.118,-19.215) 42.118,-13.449 35.223,-6.554 ; v3@41.948,-23.78 cw(c41.536,-24.192) 42.118,-24.192 cw(c42.701,-24.192) v3@42.289,-23.78 ; v3@41.948,-23.439 ccw(c41.536,-23.027) 42.118,-23.027 ccw(c42.701,-23.027) v3@42.289,-23.439 ; v3@41.948,-19.386 cw(c41.536,-19.798) 42.118,-19.798 cw(c42.701,-19.798) v3@42.289,-19.386 ; v3@41.948,-19.044 ccw(c41.536,-18.632) 42.118,-18.632 ccw(c42.701,-18.632) v3@42.289,-19.044
  Bottom Layer w0.229: v3(42.118,-19.215) 42.131,-19.202 72.192,-19.202 79.007,-26.018 LCD1.2@79.007,-28.765 ; v3@42.289,-19.386 cw(c42.732,-19.828) 42.732,-19.202 ; v3@42.289,-19.044 ccw(c42.67,-18.663) 42.67,-19.202 ; LCD1.2@78.841,-27.599 ccw(c78.438,-27.196) 79.007,-27.196 ccw(c79.576,-27.196) LCD1.2@79.174,-27.599
SEG1: LCD1.3 P4.11 U1.35 | length 78.1
  Top Layer w0.229: P4.11@35.223,-3.645 cw(c35.223,-5.18) 36.308,-4.095 cw(c37.393,-3.01) P4.11@35.859,-3.01 ; P4.11@35.223,-3.417 cw(c35.223,-4.4) 35.918,-3.705 cw(c36.613,-3.01) P4.11@35.63,-3.01 ; P4.11@35.223,-3.01 36.505,-4.292 36.505,-6.744 42.906,-13.144 v3(42.906,-19.875) 42.906,-26.429 42.626,-26.708 U1.35@39.385,-26.708 ; v3@42.735,-20.046 cw(c42.323,-20.458) 42.906,-20.458 cw(c43.488,-20.458) v3@43.076,-20.046 ; v3@42.735,-19.705 ccw(c42.323,-19.293) 42.906,-19.293 ccw(c43.488,-19.293) v3@43.076,-19.705
  Bottom Layer w0.229: v3(42.906,-19.875) 71.608,-19.875 78.007,-26.275 LCD1.3@78.007,-28.765 ; v3@43.076,-20.046 cw(c43.488,-20.458) 43.488,-19.875 cw(c43.488,-19.293) v3@43.076,-19.705 ; LCD1.3@77.841,-27.599 ccw(c77.438,-27.196) 78.007,-27.196 ccw(c78.576,-27.196) LCD1.3@78.174,-27.599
